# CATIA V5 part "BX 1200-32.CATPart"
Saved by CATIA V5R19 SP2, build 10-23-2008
Part number: BX 1200-32
Bounding box of the stored display mesh (mm): x -59.975 to 59.975, y -59.975 to 59.975, z 0 to 187
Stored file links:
  C:\Users\Bora\Desktop\3D Katı model\BX serisi\BX 1200\BX 1200-32.CATPart
  C:\Program Files\Dassault Systemes\B19\intel_a\reffiles\standard\MetricThickPitch.txt
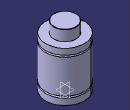
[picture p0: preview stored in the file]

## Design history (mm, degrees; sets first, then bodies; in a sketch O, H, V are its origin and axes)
Body1 (main body)
  Sketch1 on yz-plane, origin (0, 0, 0), H (0, 1, 0), V (0, 0, 1)
    point P1 (60, 130)
    point P2 (60, 135)
    arc A1 centre (60, 132.5) radius 2.5 from (60, 135) to (60, 130) ccw
    point P3 (60, 20)
    point P4 (60, 25)
    arc A2 centre (60, 22.5) radius 2.5 from (60, 25) to (60, 20) ccw
    point P5 (60, 135)
    line L1 (60, 154) -> (60, 135)
    point P8 (35, 186)
    line L2 (35, 186) -> (35, 154)
    point P10 (35, 186)
    arc A3 centre (34, 186) radius 1 from (35, 186) to (34, 187) ccw
    point P11 (60, 25)
    point P12 (60, 130)
    line L3 (60, 130) -> (60, 25)
    point P14 (60, 20)
    line L4 (60, 20) -> (60, 0)
    line L5 (34, 187) -> (0, 187)
    point P15 (0, 187)
    line L6 (35, 154) -> (60, 154)
    line L7 (60, 0) -> (0, 0)
    tangency: L5 A3
    coincidence: P15 V, P1 P12, P2 P5, P3 P14, P4 P11, P8 P10
    horizontal: L6 H, L7 H
  Shaft1: profile Sketch1, axis Sketch1.V, angle 360
  Sketch2 on face of Shaft1 from Sketch1.L7, origin (0, 0, 0), H (1, 0, 0), V (0, -1, 0)
    point P1 (32.5, 0)
    distance P1 V = 32.5
  Hole1: placed by Sketch2, at (32.5, 0, 0) direction (0, 0, 1), diameter 8.376, depth 10, threaded "M10", thread diameter 10, thread depth 10, pitch 1.5
  CircPattern1: of Hole1, instances 4, angular step 90, axis from xy-plane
